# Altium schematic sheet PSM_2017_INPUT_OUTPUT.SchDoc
size Tabloid
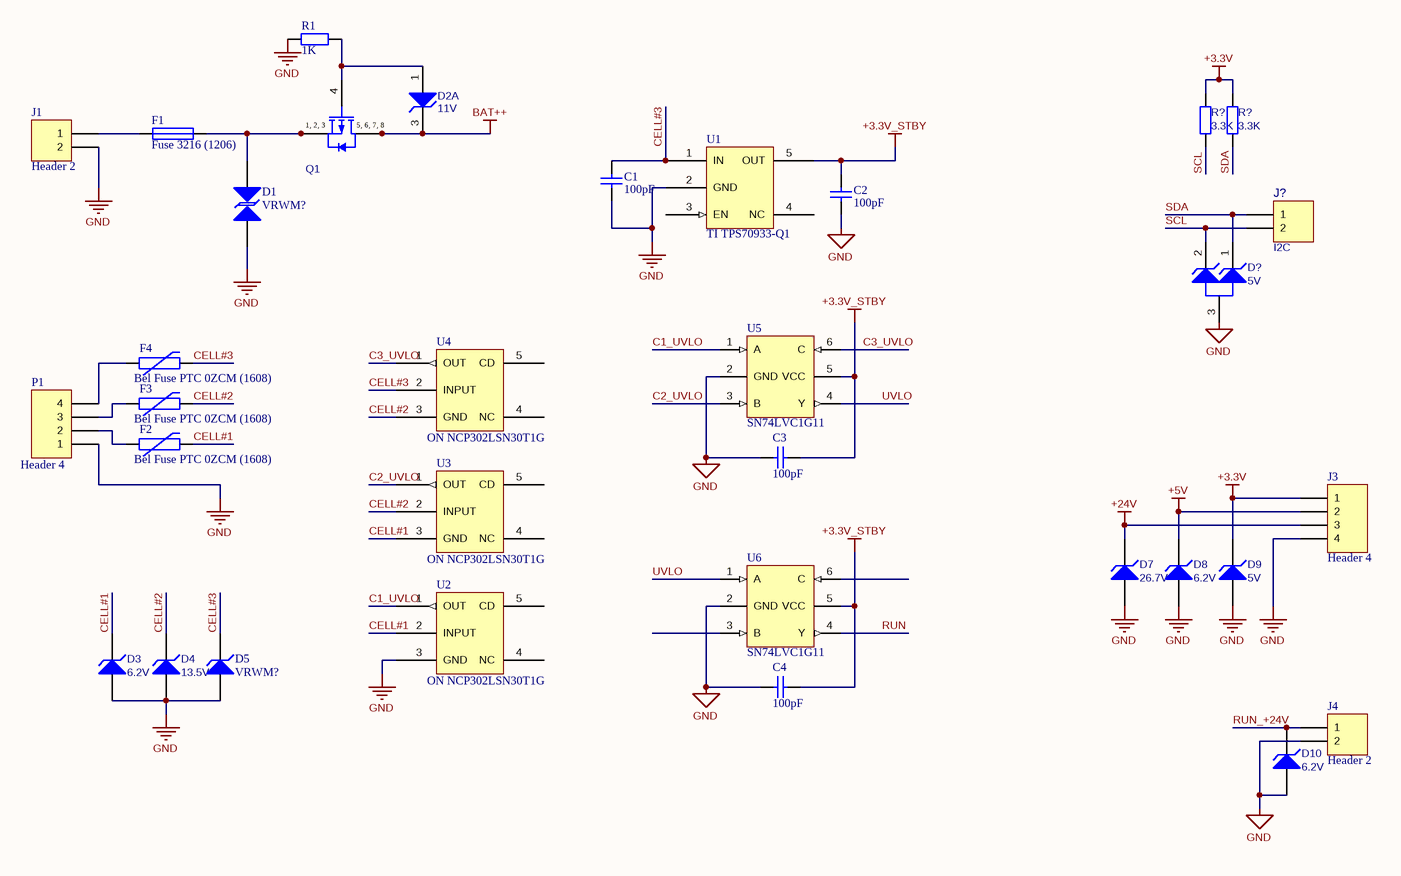
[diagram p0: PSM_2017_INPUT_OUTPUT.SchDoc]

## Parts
(Parts that share a designator on the sheet are numbered #1, #2 ... from top to bottom, then left to right.)
C1  value 100pF  [C1206]  (hidden comment: Cap Semi)
C2  value 100pF  [C1206]  (hidden comment: Cap Semi)
C3  value 100pF  [C1206]  (hidden comment: Cap Semi)
C4  value 100pF  [C1206]  (hidden comment: Cap Semi)
D1  VRWM?  [ON Semi TVS SMCJ-Series]
D2  11V  [ONSC-SOT-23-3-318-08_V]  (part A of 2)
D3  6.2V  [ONSC-SOD-923-2-514AA-01_V]
D4  13.5V  [ONSC-SOD-923-2-514AA-01_V]
D5  VRWM?  [ON Semi TVS SMCJ-Series]
D7  26.7V  [ON Semi TVS SMCJ-Series]
D8  6.2V  [ONSC-SOD-923-2-514AA-01_V]
D9  5V  [ONSC-SOD-923-2-514AA-01_V]
D10  6.2V  [ONSC-SOD-923-2-514AA-01_V]
D?  5V  [ONSC-SOT-723-3-631AA-01_V]
F1  Fuse 3216 (1206)  [Chip Fuse 3216 (1206)]
F2  Bel Fuse PTC 0ZCM (1608)  [Bel Fuse 1608 (0603) Chip]
F3  Bel Fuse PTC 0ZCM (1608)  [Bel Fuse 1608 (0603) Chip]
F4  Bel Fuse PTC 0ZCM (1608)  [Bel Fuse 1608 (0603) Chip]
J1  Header 2  [HDR1X2]
J3  Header 4  [HDR1X4]
J4  Header 2  [HDR1X2]
J?  I2C  [HDR1X2]
P1  Header 4  [HDR1X4]
Q1  BSC030P03NS3 G  [INF-PG-TDSON-8-1_V]  (value not drawn)
R1  value 1K  [AXIAL-0.4]  (hidden comment: Res2)
R?#1  value 3.3K  [RESC 2012 (0805) X06N]  (hidden comment: Res2)
R?#2  value 3.3K  [RESC 2012 (0805) X06N]  (hidden comment: Res2)
U1  TI TPS70933-Q1  [TI TPS709-Q1, SOT-23 5-Pin]
U2  ON NCP302LSN30T1G  [ON NCP30x SOT-23-5]
U3  ON NCP302LSN30T1G  [ON NCP30x SOT-23-5]
U4  ON NCP302LSN30T1G  [ON NCP30x SOT-23-5]
U5  SN74LVC1G11  [TI SC70 DCK 6-Pin]
U6  SN74LVC1G11  [TI SC70 DCK 6-Pin]

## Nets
+3.3V: D9.1(K) J3.1 R?#1.1 R?#2.1
+3.3V_STBY: C2.2 C3.1 C4.1 U1.5(OUT) U5.5(VCC) U6.5(VCC)
+5V: D8.1(K) J3.2
+24V: D7.1(K) J3.3
BAT++: D2.3(K) Q1.5(DRAIN) Q1.6(DRAIN) Q1.7(DRAIN) Q1.8(DRAIN)
GND: C1.1 C2.1 C3.2 C4.2 D1.1(K) D3.2(A) D4.2(A) D5.2(A) D7.2(A) D8.2(A) D9.2(A) D10.2(A) D?.3(A) J1.2 J3.4 J4.2 P1.1 R1.1 U1.2(GND) U2.3(GND) U5.2(GND) U6.2(GND)
C1_UVLO: U2.1(OUT) U5.1(A)
C2_UVLO: U3.1(OUT) U5.3(B)
C3_UVLO: U4.1(OUT) U5.6(C)
CELL#1: D3.1(K) F2.2 U2.2(INPUT) U3.3(GND)
CELL#2: D4.1(K) F3.2 U3.2(INPUT) U4.3(GND)
CELL#3: C1.2 D5.1(K) F4.2 U1.1(IN) U4.2(INPUT)
RUN: U6.4(Y)
RUN_+24V: D10.1(K) J4.1
SCL: D?.2(K2) J?.2 R?#1.2
SDA: D?.1(K1) J?.1 R?#2.2
UVLO: U5.4(Y) U6.1(A)
NetD1_2: D1.2(A) F1.2 Q1.1(SOURCE) Q1.2(SOURCE) Q1.3(SOURCE)
NetD2_1: D2.1(A) Q1.4(GATE) R1.2
NetF1_1: F1.1 J1.1
NetF2_1: F2.1 P1.2
NetF3_1: F3.1 P1.3
NetF4_1: F4.1 P1.4

Not connected (* = marked no-connect by the designer): U1 3(EN) 4(NC); U2 4(NC) 5(CD); U3 4(NC) 5(CD); U4 4(NC) 5(CD); U6 3(B) 6(C)

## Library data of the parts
C1-C4 = Cap Semi: Capacitor (Semiconductor SIM Model)
D1 = ON SMCJ-Series BiDirectional: ON Semi TVS Diode SMC
D2 = BZX84C11LT1G: Zener Voltage Regulator, 225 mW, 3-Pin SOT-23, Pb-Free, Tape and Reel; Manufacturer: On Semiconductor
D3 D8 D10 = ESD9X5.0ST5G: Transient Voltage Suppressor, Micro-Packaged Diode for ESD Protection, 2-Pin SOD-923, Pb-Free, Tape and Reel; Manufacturer: On Semiconductor; Direction: Unidirectional; IR Max (uA): 1; V(BR) Min (V): 6.2; VRWM Max (V): 5
D4 = ESD9X12ST5G: Transient Voltage Suppressor, Micro-Packaged Diode for ESD Protection, 2-Pin SOD-923, Pb-Free, Tape and Reel; Manufacturer: On Semiconductor; Direction: Unidirectional; IR Max (uA): 1; PPK Max (W): 140; V(BR) Min (V): 13.5; VRWM Max (V): 12
D5 = ON SMCJ-Series UniDirectional: ON Semi TVS Diode SMC
D7 = ON SMCJ-Series: ON Semi TVS Diode SMC
D9 = ESD9X3.3ST5G: Transient Voltage Suppressor, Micro-Packaged Diode for ESD Protection, 2-Pin SOD-923, Pb-Free, Tape and Reel; Manufacturer: On Semiconductor; Direction: Unidirectional; IR Max (uA): 2.5; Number of Lines: 1; V(BR) Min (V): 5; VRWM Max (V): 3.3
D? = ESD7C3.3DT5G: Transient Voltage Suppressor, Micro-Packaged Diode for ESD Protection, 3-Pin SOT-723, Pb-Free, Tape and Reel; Manufacturer: On Semiconductor; C Max (pF): 13; Direction: Unidirectional; IR Max (uA): 1; Number of Lines: 2; V(BR) Min (V): 5; VRWM Max (V): 3.3
F2-F4 = Bel Fuse PTC 0ZCM (1608): PTC Resetable Fuse
J1 J4 J? = Header 2: Header, 2-Pin
J3 P1 = Header 4: Header, 4-Pin
Q1 = BSC030P03NS3 G: P-Channel OptiMOS P3 Power-Transistor, -30 V VDS, -100 A ID, -55 to 150 degC, PG-TDSON-8-1, Reel, Green; Manufacturer: Infineon; Green: TRUE; ID (max): -100 A; IDpuls (max): -200 A; Pto t (max): 125 W; QG: 137 nC; RDS (on) (max): 3 mOhm; Rth: 1 K/W; VDS (max): -30 V; VGS(th) (max): -1.9 V; VGS(th) (min): -3.1 V
R1 R?#1 R?#2 = Res2: Resistor
U1 = TI TPS70933-Q1: 3.3V 150mA, 30Vin, Ultralow-Iq, Voltage Regulator, AEC-Q100
U2-U4 = ON NCP302LSN30T1G: Ultra Low Power Voltage Detector Series  with Programmable Delay, 3V Threshold, Push-Pull
U5 U6 = TI SN74LVC1G11DCK (SC70): SN74LVC1G11 Single 3-Input Positive-AND Gate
